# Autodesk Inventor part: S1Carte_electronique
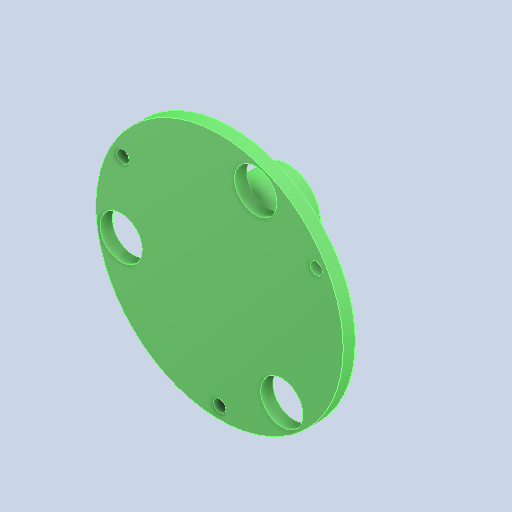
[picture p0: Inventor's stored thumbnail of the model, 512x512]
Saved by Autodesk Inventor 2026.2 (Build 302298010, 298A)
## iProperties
Created: 1601-01
Part Number: S1Carte_electronique
Material: Générique
Document SubType Name: Modeling
Designer: mel
Density: 1 g/cm^3
Appearance: Par défaut
Author: mel
Sending System: SOLIDWORKS 2023
Part Number: Carte_electronique
Last Saved Date: 2025-04-02
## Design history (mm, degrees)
feature "Boss.-Extru.4"
node "Solide1"
